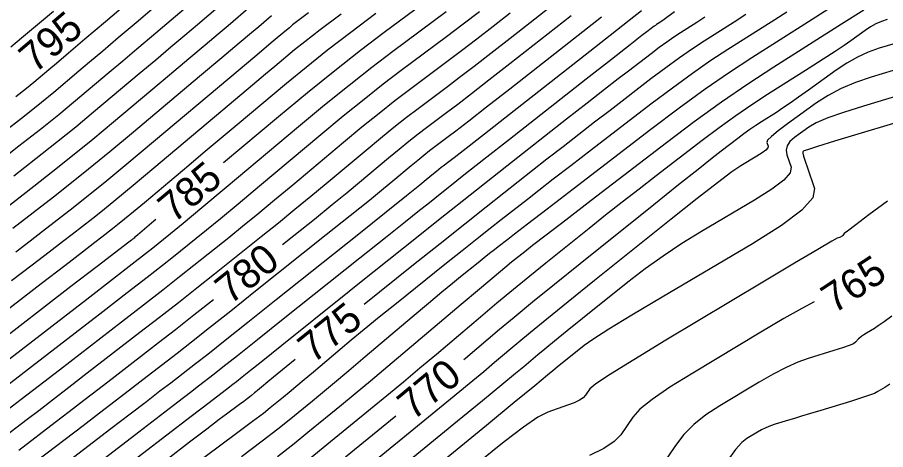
# Model space of a CAD drawing. Extents: x 2079879 to 2092887, y 778083 to 784051.
# Drawn here: x 2083954.9 to 2084037.6, y 780729.8 to 780770.9 of the extents above; entities that cross this region are included whole.
import ezdxf

# ---------------------------------------------------------------- set-up
doc = ezdxf.new("R2010")
doc.units = 0
doc.layers.add('DT_X_Contour_Major', color=7, linetype='Continuous')
doc.layers.add('DT_X_Contour_Minor', color=7, linetype='Continuous')

msp = doc.modelspace()

# ---------------------------------------------------------------- linework, layer by layer
at = {"layer": 'DT_X_Contour_Major'}
for points in [[(2083995.761, 780786.027), (2083995.407, 780785.761), (2083993.527, 780784.354), (2083991.127, 780782.563), (2083984.033, 780777.273), (2083981.605, 780775.453), (2083979.644, 780773.958), (2083978.148, 780772.789), (2083977.119, 780771.946), (2083974.995, 780770.133), (2083974.048, 780769.329), (2083972.802, 780768.275), (2083971.255, 780766.972), (2083969.409, 780765.42), (2083964.085, 780760.949), (2083962.113, 780759.308), (2083960.189, 780757.737), (2083958.314, 780756.236), (2083956.487, 780754.805), (2083951.68, 780751.082)], [(2083995.705, 780773.849), (2083989.863, 780769.487), (2083987.592, 780767.759), (2083985.159, 780765.844), (2083982.564, 780763.744), (2083979.807, 780761.458), (2083974.567, 780757.063)], [(2084024.301, 780771.193), (2084023.179, 780770.463), (2084020.328, 780768.658), (2084019.209, 780767.925), (2084017.992, 780767.081), (2084016.677, 780766.126), (2084015.263, 780765.059), (2084011.361, 780762.066), (2084009.889, 780760.933), (2084008.398, 780759.779), (2084006.889, 780758.604), (2084005.361, 780757.408), (2084001.263, 780754.192), (2083999.563, 780752.852), (2083997.536, 780751.245), (2083995.182, 780749.369), (2083992.501, 780747.227), (2083987.95, 780743.583)], [(2084007.667, 780771.088), (2084001.831, 780766.507), (2083999.821, 780764.932), (2083998.166, 780763.644), (2083996.867, 780762.643), (2083995.924, 780761.928), (2083993.883, 780760.404), (2083993.083, 780759.795), (2083992.216, 780759.112), (2083991.28, 780758.354), (2083990.277, 780757.521), (2083987.51, 780755.201), (2083986.34, 780754.231), (2083984.907, 780753.06), (2083983.209, 780751.69), (2083981.247, 780750.118), (2083980.177, 780749.264)], [(2084039.816, 780768.832), (2084036.997, 780767.984), (2084035.948, 780767.616), (2084034.916, 780767.148), (2084033.899, 780766.579), (2084032.9, 780765.911), (2084030.255, 780763.995), (2084029.321, 780763.324), (2084028.501, 780762.748), (2084027.795, 780762.268), (2084027.204, 780761.882), (2084025.78, 780760.98), (2084025.239, 780760.628), (2084024.683, 780760.246), (2084024.113, 780759.835), (2084023.528, 780759.396), (2084021.949, 780758.184), (2084021.103, 780757.524), (2084019.75, 780756.452), (2084017.89, 780754.967), (2084015.522, 780753.07), (2084008.531, 780747.462), (2084006.085, 780745.493), (2084003.989, 780743.791), (2084002.245, 780742.358), (2084000.85, 780741.193), (2083997.6, 780738.443), (2083997.452, 780738.318)], [(2083968.13, 780751.666), (2083967.938, 780751.505), (2083966.815, 780750.564), (2083966.378, 780750.197), (2083966.126, 780749.986), (2083966.04, 780749.913), (2083965.969, 780749.855), (2083965.913, 780749.809), (2083965.873, 780749.777), (2083965.787, 780749.711), (2083965.404, 780749.416), (2083964.318, 780748.582), (2083962.53, 780747.207), (2083960.039, 780745.293), (2083952.461, 780739.47), (2083949.747, 780737.368), (2083947.287, 780735.431), (2083945.082, 780733.658), (2083943.132, 780732.05), (2083938.27, 780727.979)], [(2083973.609, 780744.028), (2083971.746, 780742.555), (2083969.991, 780741.179), (2083968.372, 780739.921), (2083964.236, 780736.725), (2083962.717, 780735.552), (2083961.26, 780734.429), (2083959.867, 780733.358), (2083958.537, 780732.337), (2083955.074, 780729.682)], [(2084030.814, 780743.833), (2084029.632, 780743.214), (2084027.921, 780742.244), (2084025.729, 780740.949), (2084019.24, 780737.058), (2084017.057, 780735.702), (2084015.376, 780734.551), (2084014.197, 780733.606), (2084013.519, 780732.866), (2084012.381, 780731.168), (2084011.765, 780730.525), (2084010.77, 780729.868), (2084009.398, 780729.199)], [(2083981.394, 780738.332), (2083980.539, 780737.646), (2083979.333, 780736.674), (2083978.781, 780736.224), (2083978.185, 780735.719), (2083977.976, 780735.542), (2083977.794, 780735.39), (2083977.641, 780735.262), (2083977.515, 780735.158), (2083977.218, 780734.915), (2083977.063, 780734.792), (2083976.821, 780734.608), (2083976.493, 780734.361), (2083976.078, 780734.053), (2083974.856, 780733.147), (2083974.158, 780732.623), (2083972.981, 780731.728), (2083971.326, 780730.464), (2083969.192, 780728.829)], [(2083990.984, 780732.959), (2083986.191, 780729.034)]]:
    msp.add_lwpolyline(points, dxfattribs=at)
at = {"layer": 'DT_X_Contour_Minor'}
for points in [[(2083969.072, 780775.419), (2083963.321, 780770.509), (2083961.366, 780768.842), (2083959.816, 780767.522), (2083958.671, 780766.548), (2083957.93, 780765.922), (2083956.493, 780764.716), (2083955.798, 780764.147), (2083954.789, 780763.344)], [(2083971.084, 780774.551), (2083966.239, 780770.415), (2083964.537, 780768.964), (2083963.062, 780767.71), (2083961.817, 780766.654), (2083960.799, 780765.797), (2083958.391, 780763.775), (2083957.243, 780762.834), (2083955.604, 780761.528), (2083953.475, 780759.857)], [(2083973.096, 780773.683), (2083969.158, 780770.321), (2083967.707, 780769.085), (2083966.309, 780767.898), (2083964.963, 780766.76), (2083963.669, 780765.671), (2083960.289, 780762.833), (2083958.866, 780761.658), (2083957.132, 780760.264), (2083955.088, 780758.65), (2083952.732, 780756.816)], [(2084007.007, 780772.967), (2084001.849, 780768.918), (2084000.025, 780767.491), (2083998.423, 780766.248), (2083997.041, 780765.188), (2083995.88, 780764.312), (2083993.079, 780762.221), (2083991.982, 780761.385), (2083990.791, 780760.447), (2083989.507, 780759.407), (2083988.13, 780758.264), (2083984.333, 780755.08), (2083982.878, 780753.869), (2083981.363, 780752.624), (2083979.787, 780751.344), (2083978.15, 780750.03), (2083973.703, 780746.481), (2083972.009, 780745.135), (2083970.261, 780743.758), (2083968.46, 780742.35), (2083966.605, 780740.911), (2083961.587, 780737.033), (2083959.819, 780735.668), (2083958.279, 780734.48), (2083956.967, 780733.47), (2083955.882, 780732.636), (2083953.292, 780730.651)], [(2083975.107, 780772.815), (2083972.076, 780770.227), (2083970.878, 780769.207), (2083969.555, 780768.087), (2083968.109, 780766.866), (2083966.539, 780765.546), (2083962.187, 780761.891), (2083960.49, 780760.483), (2083958.661, 780759), (2083956.701, 780757.443), (2083954.61, 780755.81)], [(2083989.059, 780771.304), (2083986.672, 780769.501), (2083984.461, 780767.789), (2083982.426, 780766.168), (2083980.568, 780764.639), (2083975.849, 780760.681), (2083974.159, 780759.264), (2083972.628, 780757.981), (2083971.258, 780756.83), (2083970.047, 780755.814), (2083967.031, 780753.281), (2083965.993, 780752.412), (2083965.141, 780751.707), (2083964.475, 780751.163), (2083963.996, 780750.783), (2083962.966, 780749.985), (2083962.316, 780749.484), (2083961.141, 780748.58), (2083959.44, 780747.271), (2083957.212, 780745.559), (2083950.571, 780740.456)], [(2083998.936, 780771.456), (2083997.388, 780770.279), (2083995.792, 780769.081), (2083991.471, 780765.854), (2083989.778, 780764.565), (2083987.942, 780763.118), (2083985.961, 780761.513), (2083983.836, 780759.75), (2083977.978, 780754.838), (2083975.954, 780753.145), (2083974.276, 780751.75), (2083972.943, 780750.653), (2083971.956, 780749.854), (2083969.784, 780748.121), (2083968.754, 780747.307), (2083967.292, 780746.163), (2083965.397, 780744.692), (2083963.07, 780742.891), (2083956.289, 780737.651), (2083954.025, 780735.901)], [(2084001.867, 780771.329), (2084000.23, 780770.05), (2083998.679, 780768.852), (2083997.215, 780767.734), (2083995.836, 780766.696), (2083992.275, 780764.037), (2083990.88, 780762.975), (2083989.366, 780761.782), (2083987.734, 780760.46), (2083985.983, 780759.007), (2083981.156, 780754.959), (2083979.416, 780753.507), (2083977.82, 780752.187), (2083976.365, 780750.999), (2083975.053, 780749.942), (2083971.744, 780747.301), (2083970.382, 780746.221), (2083968.776, 780744.961), (2083966.928, 780743.521), (2083964.838, 780741.901), (2083958.938, 780737.342), (2083956.922, 780735.784), (2083955.298, 780734.531), (2083954.066, 780733.581)], [(2083995.749, 780771.465), (2083990.667, 780767.671), (2083988.677, 780766.155), (2083986.517, 780764.453), (2083984.188, 780762.566), (2083981.69, 780760.493), (2083974.801, 780754.717), (2083972.492, 780752.783), (2083970.732, 780751.313), (2083969.521, 780750.308), (2083968.859, 780749.766), (2083967.825, 780748.941), (2083967.141, 780748.403), (2083965.864, 780747.41), (2083963.994, 780745.962), (2083961.532, 780744.058), (2083954.174, 780738.372)], [(2083958.373, 780771.491), (2083955.332, 780768.939), (2083954.307, 780768.082)], [(2083985.752, 780771.243), (2083983.763, 780769.734), (2083982.289, 780768.593), (2083981.329, 780767.82), (2083979.456, 780766.249), (2083978.571, 780765.506), (2083977.319, 780764.456), (2083975.7, 780763.097), (2083973.716, 780761.431), (2083967.935, 780756.576), (2083965.946, 780754.911), (2083964.313, 780753.559), (2083963.037, 780752.518), (2083962.119, 780751.788), (2083960.144, 780750.26), (2083959.229, 780749.552), (2083957.964, 780748.578), (2083956.349, 780747.335), (2083954.385, 780745.825)], [(2083982.659, 780771.364), (2083981.894, 780770.789), (2083981.388, 780770.404), (2083981.142, 780770.21), (2083980.832, 780769.945), (2083980.389, 780769.572), (2083979.295, 780768.652), (2083977.548, 780767.184), (2083975.149, 780765.169), (2083967.881, 780759.066), (2083965.36, 780756.958), (2083963.246, 780755.209), (2083961.54, 780753.821), (2083960.241, 780752.794), (2083957.323, 780750.534), (2083956.142, 780749.621), (2083954.787, 780748.576)], [(2084014.363, 780771.543), (2084013.174, 780770.614), (2084011.382, 780769.21), (2084008.987, 780767.331), (2084001.795, 780761.685), (2083999.411, 780759.814), (2083997.652, 780758.437), (2083996.519, 780757.551), (2083996.011, 780757.159), (2083995.49, 780756.77), (2083995.286, 780756.615), (2083995.065, 780756.441), (2083994.826, 780756.247), (2083994.57, 780756.035), (2083993.865, 780755.443), (2083993.265, 780754.955), (2083991.994, 780753.934), (2083990.053, 780752.381), (2083987.441, 780750.295), (2083979.581, 780744.022), (2083976.891, 780741.877), (2083974.716, 780740.149), (2083973.054, 780738.837), (2083971.907, 780737.942), (2083969.534, 780736.108), (2083968.511, 780735.319), (2083967.222, 780734.327), (2083965.668, 780733.134), (2083963.847, 780731.738), (2083958.639, 780727.745)], [(2084017.516, 780771.459), (2084016.507, 780770.723), (2084016.097, 780770.431), (2084015.802, 780770.244), (2084015.686, 780770.168), (2084015.56, 780770.081), (2084015.424, 780769.982), (2084015.277, 780769.871), (2084014.873, 780769.561), (2084014.399, 780769.191), (2084013.278, 780768.313), (2084011.512, 780766.928), (2084009.099, 780765.035), (2084001.804, 780759.31), (2083999.348, 780757.381), (2083997.451, 780755.89), (2083996.113, 780754.834), (2083995.333, 780754.216), (2083994, 780753.148), (2083993.221, 780752.526), (2083991.884, 780751.458), (2083989.99, 780749.946), (2083987.538, 780747.988), (2083980.255, 780742.176), (2083977.796, 780740.214), (2083975.879, 780738.69), (2083974.505, 780737.603), (2083973.675, 780736.952), (2083972.183, 780735.799), (2083971.408, 780735.202), (2083970.204, 780734.277), (2083968.568, 780733.022), (2083966.503, 780731.438), (2083960.421, 780726.776)], [(2084028.198, 780771.428), (2084026.72, 780770.479), (2084022.591, 780767.865), (2084020.971, 780766.804), (2084019.209, 780765.581), (2084017.304, 780764.198), (2084015.256, 780762.653), (2084009.605, 780758.318), (2084007.634, 780756.803), (2084005.958, 780755.511), (2084004.577, 780754.442), (2084003.492, 780753.595), (2084000.992, 780751.633), (2083999.955, 780750.816), (2083998.719, 780749.835), (2083997.283, 780748.691), (2083995.648, 780747.384), (2083991.021, 780743.681), (2083989.385, 780742.365), (2083987.944, 780741.196), (2083986.701, 780740.173), (2083985.653, 780739.297), (2083983.122, 780737.155), (2083982.232, 780736.404), (2083981.461, 780735.756), (2083980.809, 780735.213), (2083980.276, 780734.773), (2083979.012, 780733.739), (2083978.354, 780733.219), (2083977.328, 780732.436), (2083975.934, 780731.389), (2083974.172, 780730.079), (2083968.981, 780726.233)], [(2084032.095, 780771.663), (2084030.261, 780770.495), (2084024.854, 780767.072), (2084022.733, 780765.682), (2084020.425, 780764.081), (2084017.93, 780762.269), (2084015.249, 780760.246), (2084007.849, 780754.57), (2084005.379, 780752.674), (2084003.518, 780751.244), (2084002.266, 780750.28), (2084001.623, 780749.782), (2084000.722, 780749.074), (2084000.348, 780748.78), (2083999.902, 780748.426), (2083999.384, 780748.013), (2083998.794, 780747.542), (2083997.126, 780746.207), (2083996.369, 780745.591), (2083995.35, 780744.747), (2083994.069, 780743.673), (2083992.525, 780742.37), (2083988.058, 780738.591), (2083986.488, 780737.265), (2083985.127, 780736.123), (2083983.977, 780735.164), (2083983.036, 780734.388), (2083980.807, 780732.562), (2083979.745, 780731.719), (2083978.231, 780730.556), (2083976.266, 780729.076)], [(2084035.541, 780771.613), (2084033.417, 780770.267), (2084026.952, 780766.174), (2084024.494, 780764.573), (2084021.971, 780762.84), (2084019.382, 780760.976), (2084016.727, 780758.98), (2084009.559, 780753.481), (2084007.149, 780751.63), (2084005.293, 780750.2), (2084003.992, 780749.192), (2084003.245, 780748.604), (2084001.994, 780747.601), (2084001.342, 780747.067), (2084000.326, 780746.22), (2083998.944, 780745.058), (2083997.197, 780743.583), (2083992.051, 780739.229), (2083990.213, 780737.678), (2083988.558, 780736.29), (2083987.086, 780735.065), (2083985.796, 780734.002), (2083982.601, 780731.386), (2083981.275, 780730.322), (2083979.694, 780729.092)], [(2083979.13, 780771.078), (2083977.913, 780770.039), (2083977.219, 780769.45), (2083976.048, 780768.464), (2083974.402, 780767.078), (2083972.279, 780765.295), (2083965.983, 780760.008), (2083963.736, 780758.133), (2083961.717, 780756.473), (2083959.927, 780755.029), (2083958.364, 780753.799), (2083954.501, 780750.808)], [(2084010.546, 780770.95), (2084008.327, 780769.21), (2084001.813, 780764.096), (2083999.616, 780762.373), (2083997.909, 780761.04), (2083996.693, 780760.097), (2083995.967, 780759.544), (2083994.686, 780758.587), (2083994.185, 780758.205), (2083993.64, 780757.776), (2083993.053, 780757.3), (2083992.424, 780756.778), (2083990.687, 780755.322), (2083989.803, 780754.593), (2083988.45, 780753.497), (2083986.631, 780752.035), (2083984.344, 780750.206), (2083977.622, 780744.842), (2083975.264, 780742.963), (2083973.231, 780741.352), (2083971.523, 780740.008), (2083970.14, 780738.931), (2083966.885, 780736.416), (2083965.614, 780735.435), (2083964.241, 780734.378), (2083962.767, 780733.246), (2083961.192, 780732.037), (2083956.856, 780728.714)], [(2084020.404, 780770.958), (2084019.638, 780770.447), (2084018.065, 780769.451), (2084017.448, 780769.046), (2084016.776, 780768.581), (2084016.05, 780768.054), (2084015.27, 780767.465), (2084013.117, 780765.813), (2084012.144, 780765.062), (2084010.838, 780764.046), (2084009.2, 780762.766), (2084007.23, 780761.222), (2084001.534, 780756.751), (2083999.404, 780755.075), (2083997.286, 780753.401), (2083995.18, 780751.728), (2083993.087, 780750.056), (2083987.52, 780745.601), (2083985.554, 780744.027), (2083983.831, 780742.648), (2083982.35, 780741.465), (2083981.112, 780740.476), (2083978.133, 780738.098), (2083977.127, 780737.296), (2083976.344, 780736.673), (2083975.782, 780736.228), (2083975.442, 780735.962), (2083974.832, 780735.491), (2083974.306, 780735.086), (2083973.185, 780734.226), (2083971.469, 780732.91), (2083969.158, 780731.138), (2083962.203, 780725.807)], [(2084037.754, 780770.737), (2084037.215, 780770.548), (2084036.684, 780770.307), (2084036.162, 780770.015), (2084035.648, 780769.671), (2084034.288, 780768.686), (2084033.657, 780768.246), (2084032.784, 780767.664), (2084031.668, 780766.94), (2084030.31, 780766.075), (2084026.366, 780763.577), (2084024.867, 780762.6), (2084023.327, 780761.543), (2084021.747, 780760.406), (2084020.127, 780759.188), (2084015.754, 780755.833), (2084014.126, 780754.577), (2084012.522, 780753.326), (2084010.941, 780752.079), (2084009.384, 780750.837), (2084005.263, 780747.531), (2084003.714, 780746.28), (2084002.157, 780745.006), (2084000.594, 780743.708), (2083999.024, 780742.388), (2083994.826, 780738.836), (2083993.253, 780737.511), (2083991.684, 780736.199), (2083990.119, 780734.901), (2083988.557, 780733.617), (2083984.396, 780730.21), (2083982.806, 780728.926)], [(2084040.429, 780766.492), (2084036.24, 780765.231), (2084034.736, 780764.723), (2084033.366, 780764.146), (2084032.129, 780763.5), (2084031.025, 780762.784), (2084028.262, 780760.781), (2084027.361, 780760.107), (2084026.73, 780759.587), (2084026.371, 780759.221), (2084026.283, 780759.009), (2084026.41, 780758.649), (2084026.379, 780758.488), (2084026.193, 780758.276), (2084025.851, 780758.013), (2084025.353, 780757.698), (2084023.818, 780756.791), (2084022.972, 780756.218), (2084021.585, 780755.181), (2084019.657, 780753.68), (2084017.188, 780751.715), (2084009.883, 780745.855), (2084007.378, 780743.84), (2084005.342, 780742.193), (2084003.775, 780740.912), (2084002.677, 780739.998), (2084000.374, 780738.049), (2083999.333, 780737.176), (2083997.936, 780736.018), (2083996.184, 780734.575), (2083994.077, 780732.846), (2083987.985, 780727.858)], [(2084041.042, 780764.151), (2084035.483, 780762.478), (2084033.595, 780761.882), (2084032.099, 780761.351), (2084030.997, 780760.883), (2084030.286, 780760.479), (2084028.916, 780759.486), (2084028.486, 780759.105), (2084028.224, 780758.705), (2084028.129, 780758.287), (2084028.201, 780757.85), (2084028.618, 780756.662), (2084028.517, 780756.131), (2084027.903, 780755.432), (2084026.774, 780754.563), (2084025.132, 780753.525), (2084020.069, 780750.532), (2084018.205, 780749.388), (2084016.414, 780748.202), (2084014.694, 780746.972), (2084013.046, 780745.7), (2084008.746, 780742.251), (2084007.271, 780741.065), (2084006.073, 780740.095), (2084005.15, 780739.341), (2084004.504, 780738.803), (2084003.148, 780737.656), (2084002.372, 780737.009), (2084001.062, 780735.927), (2083999.217, 780734.411), (2083996.838, 780732.461), (2083989.78, 780726.682)], [(2084041.757, 780761.84), (2084034.964, 780759.796), (2084032.731, 780759.122), (2084031.126, 780758.632), (2084030.15, 780758.326), (2084029.801, 780758.203), (2084029.708, 780758.124), (2084029.709, 780758.005), (2084029.784, 780757.711), (2084029.932, 780757.24), (2084030.154, 780756.593), (2084030.841, 780754.633), (2084030.663, 780753.751), (2084029.616, 780752.578), (2084027.699, 780751.111), (2084024.912, 780749.353), (2084016.319, 780744.274), (2084013.439, 780742.559), (2084011.243, 780741.222), (2084009.731, 780740.264), (2084008.903, 780739.685), (2084007.608, 780738.646), (2084007.164, 780738.289), (2084006.803, 780737.997), (2084006.525, 780737.77), (2084006.331, 780737.608), (2084005.922, 780737.263), (2084005.412, 780736.841), (2084004.188, 780735.836), (2084002.25, 780734.248), (2083999.598, 780732.076), (2083991.574, 780725.505)], [(2084037.768, 780753.417), (2084036.018, 780752.115), (2084034.751, 780751.167), (2084033.968, 780750.572), (2084033.669, 780750.331), (2084033.514, 780750.159), (2084033.452, 780750.1), (2084033.383, 780750.049), (2084033.307, 780750.009), (2084033.224, 780749.978), (2084032.993, 780749.907), (2084032.485, 780749.625), (2084031.133, 780748.83), (2084028.937, 780747.524), (2084025.898, 780745.705), (2084016.67, 780740.172), (2084013.623, 780738.327), (2084011.402, 780736.944), (2084010.007, 780736.022), (2084009.439, 780735.56), (2084009.027, 780734.944), (2084008.803, 780734.711), (2084008.443, 780734.473), (2084007.945, 780734.23), (2084007.31, 780733.983), (2084005.434, 780733.317), (2084004.504, 780732.84), (2084003.119, 780731.907), (2084001.281, 780730.518), (2083998.988, 780728.675)], [(2084038.188, 780742.481), (2084037.456, 780741.935), (2084036.905, 780741.542), (2084036.536, 780741.301), (2084035.793, 780740.862), (2084035.536, 780740.703), (2084035.323, 780740.556), (2084035.153, 780740.422), (2084035.026, 780740.299), (2084034.746, 780739.988), (2084034.538, 780739.851), (2084034.126, 780739.672), (2084033.509, 780739.453), (2084032.686, 780739.192), (2084030.221, 780738.441), (2084029.236, 780738.09), (2084028.131, 780737.598), (2084026.905, 780736.965), (2084025.559, 780736.192), (2084021.809, 780733.944), (2084020.491, 780733.076), (2084019.35, 780732.158), (2084018.386, 780731.19), (2084017.599, 780730.172), (2084015.735, 780727.392)], [(2084037.992, 780735.993), (2084037.531, 780735.676), (2084036.876, 780735.289), (2084036.529, 780735.122), (2084035.978, 780734.91), (2084035.223, 780734.655), (2084034.264, 780734.355), (2084031.436, 780733.498), (2084030.448, 780733.198), (2084029.607, 780732.943), (2084028.913, 780732.732), (2084028.364, 780732.565), (2084027.098, 780732.18), (2084026.635, 780732.025), (2084026.196, 780731.849), (2084025.781, 780731.653), (2084025.39, 780731.436), (2084024.379, 780730.83), (2084023.926, 780730.45), (2084023.325, 780729.765), (2084022.576, 780728.774)]]:
    msp.add_lwpolyline(points, dxfattribs=at)

# ---------------------------------------------------------------- texts
at = {"layer": 'DT_X_Contour_Major'}
for s, rotation, p in [('795', 40.44993, (2083956.609, 780765.528)), ('785', 39.97936, (2083969.824, 780751.259)), ('780', 38.56763, (2083975.199, 780743.502)), ('765', 33.36582, (2084032.69, 780742.657)), ('775', 38.6948, (2083983.095, 780737.902)), ('770', 39.64524, (2083992.608, 780732.467))]:
    msp.add_text(s, height=2.8, rotation=rotation, dxfattribs=at).set_placement(p)

doc.saveas('drawing.dxf')
